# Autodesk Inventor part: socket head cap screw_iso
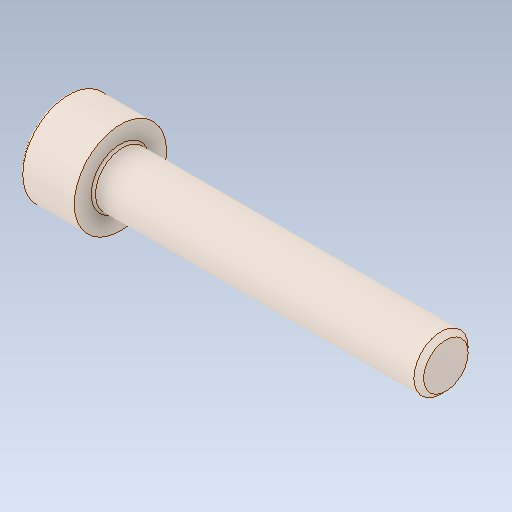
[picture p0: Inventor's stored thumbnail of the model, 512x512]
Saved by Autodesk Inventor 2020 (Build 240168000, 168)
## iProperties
Created: 1999-08
Part Number: socket head cap screw_iso
Material: Ogólny
Document SubType Name: Modeling
Designer: Tomasz
Density: 1 g/cm^3
Appearance: Domyślna
Sending System: SolidWorks 2017
Last Author: Tomasz
Last Saved: 2017-11-19
Author: Tomasz
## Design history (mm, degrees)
feature "Hex"
node "Bryła1"
